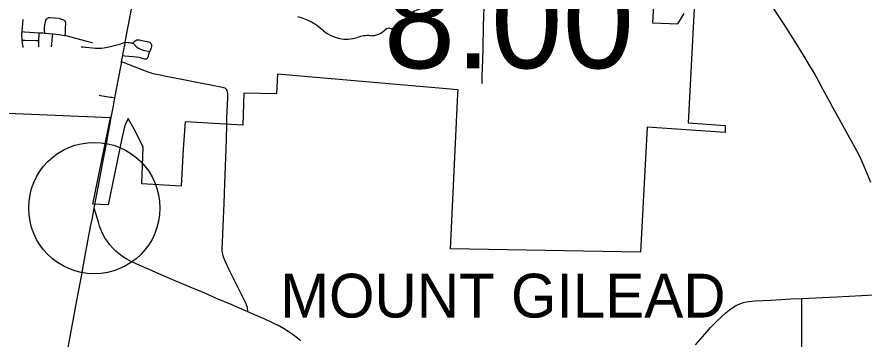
# Model space of a CAD drawing. Extents: x 1813937 to 1948437, y 826606 to 1022856.
# Drawn here: x 1875617 to 1885299, y 923462 to 927139 of the extents above; entities that cross this region are included whole.
import ezdxf

# ---------------------------------------------------------------- set-up
doc = ezdxf.new("R2010")
doc.units = 0
for name, color, linetype in [('Default', 7, 'Continuous'), ('GM_X_City_Street', 7, 'Continuous'), ('GM_X_Corporation', 7, 'Continuous'), ('GM_X_Corporation_Text', 7, 'Continuous'), ('GM_X_County_Road', 7, 'Continuous'), ('GM_X_State_Route', 7, 'Continuous'), ('GM_X_State_Shield', 7, 'Continuous'), ('GM_X_Township_Road', 7, 'Continuous'), ('GM_X_US_Route', 7, 'Continuous')]:
    doc.layers.add(name, color=color, linetype=linetype)

msp = doc.modelspace()

# ---------------------------------------------------------------- linework, layer by layer
at = {"layer": 'Default'}
msp.add_circle((1876500.9, 924957.7), 750, dxfattribs=at)
at = {"layer": 'GM_X_City_Street'}
for points in [[(1880932.1, 926381.2), (1880935.7, 926463.2), (1880938.8, 926545.4), (1880942.1, 926659.5), (1880945.3, 926765.5), (1880946.1, 926801.9), (1880950.9, 927022.4), (1880954.2, 927151.8), (1880958.8, 927335.8), (1880959.6, 927367.1), (1880961.7, 927399.1), (1880963.9, 927448.7), (1880970, 927533.8), (1880975.6, 927609.3), (1880979.7, 927650.1), (1880984.7, 927700.5), (1880992.9, 927756.8), (1881001.5, 927811.2), (1881006.5, 927839.2), (1881013.3, 927877.8)], [(1876854.6, 926851), (1876888.6, 926849), (1876905, 926845.9), (1876921.2, 926842.7), (1876929.4, 926840.6), (1876936.9, 926838), (1876941.3, 926836.1)], [(1876941.3, 926836.1), (1876955.3, 926853.2), (1876968.6, 926867), (1876979, 926874.5), (1876986.1, 926877), (1876994.5, 926878.4), (1877002.4, 926878.4), (1877017.6, 926876.9), (1877063.6, 926868.2), (1877108.6, 926858.5), (1877124.5, 926854.3), (1877133.2, 926850.2), (1877138.9, 926846.1), (1877144.2, 926841.1), (1877150, 926833.9), (1877153.4, 926825.9), (1877154.5, 926818.3), (1877154.5, 926810), (1877153.5, 926801.7), (1877149.3, 926785.6), (1877134.6, 926745.8)], [(1876941.3, 926836.1), (1876943.8, 926835.1), (1876951.5, 926831.1), (1876956.3, 926827.2), (1876961.2, 926822.2), (1876966.1, 926816.1), (1876972, 926808.5), (1876977.9, 926801.8), (1876985.3, 926794.7), (1876998.5, 926784.8), (1877013.1, 926777.1), (1877028.5, 926770.8), (1877060.4, 926761.1), (1877134.6, 926745.8)], [(1876826.1, 926698.3), (1876850.4, 926696.2), (1876897.2, 926692.3), (1876943.4, 926688.4), (1876982.4, 926684.1), (1877009.2, 926680.6), (1877025.9, 926676.7), (1877043.1, 926670.3), (1877056.3, 926665.5), (1877069.9, 926661.8), (1877081.1, 926660.5), (1877092.8, 926661.2), (1877098, 926662.6), (1877102.4, 926665), (1877107.8, 926669.7), (1877112.6, 926677.3), (1877115.5, 926685.6), (1877119.2, 926696.3), (1877125.3, 926713.7), (1877134.6, 926745.8)], [(1878015.6, 925916.7), (1878017.5, 925987.4), (1878025.2, 926216.1), (1878026, 926265.5), (1878024, 926282.5), (1878018.8, 926299.1), (1878012.2, 926310.9), (1878005.2, 926318.7), (1877995.3, 926325.4), (1877979.1, 926331.6), (1877946.8, 926339.1), (1877834.3, 926359.8), (1877690.3, 926388.5), (1877482, 926429.6), (1877361, 926451.5), (1877303.7, 926462.7), (1877253.3, 926473.1), (1877213.4, 926481.8), (1877190.8, 926487), (1877162.4, 926494.9), (1877141.3, 926501.8), (1877116.3, 926510.4), (1877010.1, 926552.4), (1876842.5, 926617.1), (1876813.5, 926628.3)]]:
    msp.add_lwpolyline(points, dxfattribs=at)
at = {"layer": 'GM_X_Corporation'}
for points in [[(1882897.8, 927411.7), (1882880.2, 927071.6), (1883171.5, 927061.4), (1883242.3, 927179.3)], [(1883362.2, 927308.2), (1883290.1, 925930.2), (1883712.1, 925900.7), (1883710.7, 925818.8), (1882818, 925881.1), (1882743.4, 924455), (1880573.7, 924490.9), (1880656.7, 926260.4), (1880659.1, 926305.9), (1878595.4, 926486.2), (1878583.6, 926260.4), (1878208.7, 926270), (1878199.8, 925904.3), (1877540.2, 925941.4), (1877516.8, 925630.4), (1877493.4, 925207.8), (1877044.7, 925233.1), (1877060.9, 925652.3), (1876991.1, 925792.1), (1876956.9, 925856.9), (1876887.2, 925978.2), (1876849.9, 925900.1), (1876815.8, 925750.3), (1876659.9, 924993.2), (1876482.9, 925000), (1876684.6, 925989.2), (1875415.8, 926039.1)]]:
    msp.add_lwpolyline(points, dxfattribs=at)
at = {"layer": 'GM_X_County_Road'}
for points in [[(1875934.1, 926954.4), (1875933.6, 926987.5), (1875933.2, 927020.2), (1875938.5, 927068.9), (1875941.6, 927085), (1875946.7, 927100.6), (1875954.9, 927114.7), (1875967, 927125.1), (1875981.9, 927131), (1875991.5, 927132)], [(1875991.5, 927132), (1875998.1, 927132.8), (1876047.2, 927128.5), (1876094.4, 927123.7), (1876125.7, 927115.3), (1876141.2, 927109.6), (1876155.5, 927101.8), (1876166.2, 927089.9), (1876168, 927085)], [(1875676.9, 926972.9), (1875687.8, 927109.6)], [(1876168, 927085), (1876171.6, 927075.1), (1876172.3, 927058.8), (1876169.7, 927010.1), (1876167.6, 926977.3), (1876166.4, 926961), (1876163.9, 926927.8)], [(1875676.7, 926874), (1875675.2, 926882.3), (1875673.6, 926931), (1875676.9, 926972.9)], [(1875676.9, 926972.9), (1875703.8, 926971), (1875872, 926959.2)], [(1875868.7, 926870.1), (1875871.2, 926937.2), (1875872, 926959.2)], [(1875872, 926959.2), (1875916.4, 926956.1), (1875934.1, 926954.4)], [(1875934.1, 926954.4), (1876026.4, 926945.7)], [(1876013.4, 926798), (1876016.6, 926833.9), (1876024, 926918.1), (1876026.4, 926945.7)], [(1876026.4, 926945.7), (1876095.9, 926939.2), (1876163.9, 926927.8)], [(1875676.7, 926874), (1875696.1, 926873.1), (1875712.1, 926872.3), (1875839.8, 926870.5), (1875868.7, 926870.1)], [(1875686.2, 926792.1), (1875683.3, 926816.9), (1875676.7, 926874)], [(1875866, 926797.2), (1875867.3, 926831.9), (1875868.7, 926870.1)], [(1876163.9, 926927.8), (1876176.7, 926925.6), (1876287.8, 926897.1), (1876414.4, 926863.6), (1876430.3, 926859.9), (1876477.1, 926848.7), (1876481.8, 926847.8)], [(1876409.4, 926792.5), (1876515.6, 926784), (1876582.1, 926784.5), (1876631.5, 926790.4), (1876684.6, 926801.2), (1876745, 926815.9), (1876790.9, 926828.5), (1876854.6, 926851)], [(1876352.6, 926797.1), (1876373.6, 926796.5), (1876399.7, 926793.3), (1876409.4, 926792.5)], [(1876554.8, 926246.6), (1876573.2, 926243.4), (1876685.6, 926224.3), (1876702.2, 926222), (1876736.9, 926217.3)], [(1878254.2, 923773.2), (1878254.3, 923790.5), (1878253, 923808.7), (1878250.6, 923823.9), (1878245.4, 923839.9), (1878232.5, 923870.5), (1878190.2, 923956.3), (1878123.3, 924091.9), (1878042.4, 924253.8), (1877999.8, 924342.4), (1877981.3, 924387.7), (1877972.5, 924412.2), (1877968.1, 924430.4), (1877964.9, 924450.4), (1877962.8, 924466.3), (1877961.8, 924498.6), (1877965, 924564.1), (1877977.3, 924843.4), (1877983.9, 925007.7), (1877992.4, 925237.8), (1878010.5, 925730.7), (1878015.6, 925916.7)]]:
    msp.add_lwpolyline(points, dxfattribs=at)
at = {"layer": 'GM_X_State_Route'}
msp.add_lwpolyline([(1878862.6, 923440.5), (1878824.6, 923472), (1878772.2, 923511.8), (1878718.1, 923549.3), (1878662.2, 923584.2), (1878619, 923608.2), (1878545.6, 923645.1), (1878441, 923692.7), (1878254.2, 923773.2), (1878064.4, 923854.7), (1877898.4, 923925.3), (1877763.1, 923984), (1877597, 924054.1), (1877400.2, 924136.2), (1877265.2, 924195.4), (1877099.6, 924266.5), (1876980, 924319.7), (1876906.6, 924355.4), (1876864.1, 924379.3), (1876823.2, 924405.9), (1876784.1, 924435.1), (1876747, 924466.8), (1876712.2, 924501), (1876679.8, 924537.7), (1876650, 924576.3), (1876623, 924617), (1876599.3, 924659.7), (1876578.8, 924704), (1876561.5, 924749.7), (1876547.5, 924796.5), (1876533.6, 924847.5), (1876498.9, 924954.6)], dxfattribs=at)
at = {"layer": 'GM_X_State_Shield'}
for centre, radius, start, end in [((1880352, 926848.2), 404.5, 94.40312, 142.57675), ((1878665.4, 926492.1), 667.2, 47.18416, 75.83597), ((1879839.5, 927236.7), 238.6, 282.87319, 323.27711), ((1879387, 927309.1), 423.3, 230.70037, 286.29184), ((1879662.5, 927150.8), 225.6, 268.77702, 315.54927), ((1879866.6, 926946.2), 63.5, 65.75173, 132.64842), ((1879631.6, 926578.5), 347.9, 85.69512, 111.20995)]:
    msp.add_arc(centre, radius, start, end, dxfattribs=at)
at = {"layer": 'GM_X_Township_Road'}
for points in [[(1885376.1, 925250.1), (1885280.3, 925476.9), (1885246.2, 925551.7), (1885216.5, 925610.5), (1885137.2, 925754.2), (1885034.3, 925941.1), (1884947, 926099.1), (1884907.6, 926171), (1884829, 926315), (1884782.3, 926401.6), (1884726.5, 926502.1), (1884669.2, 926601.6), (1884626.5, 926671.7), (1884486.8, 926894), (1884381, 927060.1), (1884210.2, 927320.9), (1884161, 927400.2), (1884138.2, 927438.6)], [(1884585.8, 923925.2), (1884986.1, 923943), (1885412.1, 923967.6), (1885559.3, 923978.2), (1885914.9, 924010.8)], [(1883371.6, 923394.4), (1883478, 923519.4), (1883543.6, 923593.1), (1883612, 923664.2), (1883671.3, 923721.2), (1883720.8, 923764.6), (1883759.4, 923795.6), (1883800.3, 923823.8), (1883828.9, 923840.5), (1883858.6, 923855.1), (1883889.3, 923867.7), (1883921, 923877.9), (1883953.3, 923885.5), (1883986, 923890.6), (1884051.7, 923896.5), (1884232, 923907.1), (1884461.5, 923919.7), (1884585.8, 923925.2)], [(1884582.7, 923237.6), (1884585.9, 923499.8), (1884585.8, 923737.8), (1884585.8, 923841.1), (1884585.8, 923893), (1884585.8, 923925.2)]]:
    msp.add_lwpolyline(points, dxfattribs=at)
at = {"layer": 'GM_X_US_Route'}
for points in [[(1876853.7, 926845.7), (1876854.6, 926851), (1876870.4, 926932.3), (1876902.8, 927110.1), (1876921, 927207.1), (1876936.8, 927287.7), (1876957.4, 927400.7), (1876999.4, 927621.4), (1877015.5, 927706.4), (1877039.5, 927835.2), (1877071.2, 928013.1), (1877081.7, 928067.3)], [(1876694.2, 925990.6), (1876719.8, 926124.7), (1876736.9, 926217.3), (1876743.7, 926254), (1876774, 926415.5), (1876810.2, 926609.3), (1876813.5, 926628.3), (1876826.1, 926698.3), (1876831, 926724.1), (1876851.9, 926835.1), (1876853.7, 926845.7)], [(1876498.9, 924954.6), (1876579.5, 925374.7), (1876606.6, 925519.3), (1876624.1, 925615.8), (1876642.7, 925712.1), (1876694.2, 925990.6)], [(1875592.7, 920234.7), (1875682, 920685.3), (1875719.9, 920878.6), (1875815.2, 921361.5), (1875889.3, 921731.6), (1876001.4, 922311.5), (1876031.4, 922472.7), (1876079.9, 922730.6), (1876119.2, 922940.2), (1876208.4, 923407.6), (1876265.9, 923714), (1876290, 923842.9), (1876353, 924181.4), (1876389.7, 924374.7), (1876432.2, 924600.4), (1876462.8, 924761.7), (1876475.9, 924828.3), (1876498.9, 924954.6)]]:
    msp.add_lwpolyline(points, dxfattribs=at)

# ---------------------------------------------------------------- texts
at = {"layer": 'Default'}
msp.add_text('8.00', height=1100, dxfattribs=at).set_placement((1879807.9, 926553.7))
at = {"layer": 'GM_X_Corporation_Text'}
msp.add_text('MOUNT GILEAD', height=500, rotation=0.00001, dxfattribs=at).set_placement((1878626.3, 923707.4))

doc.saveas('drawing.dxf')
